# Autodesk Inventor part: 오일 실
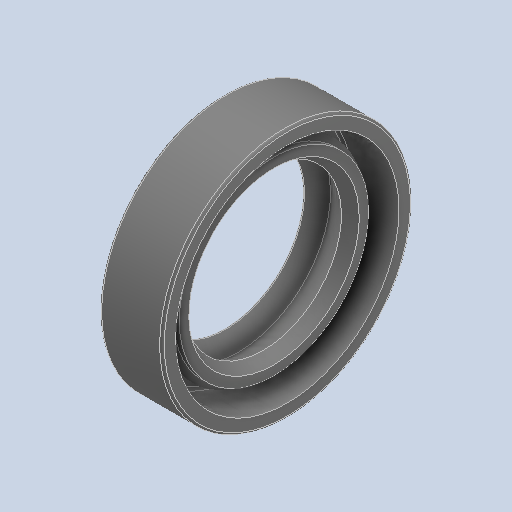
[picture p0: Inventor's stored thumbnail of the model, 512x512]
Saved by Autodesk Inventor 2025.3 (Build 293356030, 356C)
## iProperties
Created: 2025-08
Part Number: 오일 실
Material: 고무
Description: 오일-실
Document SubType Name: Modeling
Designer: infra011
Density: 0.93 g/cm^3
Appearance: 기본값
Author: jhkim
Sending System: Autodesk Inventor 2026
Preprocessor: ST-DEVELOPER v20.1
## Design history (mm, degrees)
feature "Solid1"
node "솔리드1"
